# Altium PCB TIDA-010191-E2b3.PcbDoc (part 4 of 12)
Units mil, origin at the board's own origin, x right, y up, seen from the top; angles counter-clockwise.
Board outline 9842.52 x 9842.4 mil, 6 copper layers (Layer 1 - Top Layer, Layer 2 - GND Layer, Layer 3 - Signal, Layer 4 - Signal, Layer 5 - GND, Bottom Layer), stack 59.9 mil thick; 1178 components, 642 nets, 3329 pads, 2967 vias.
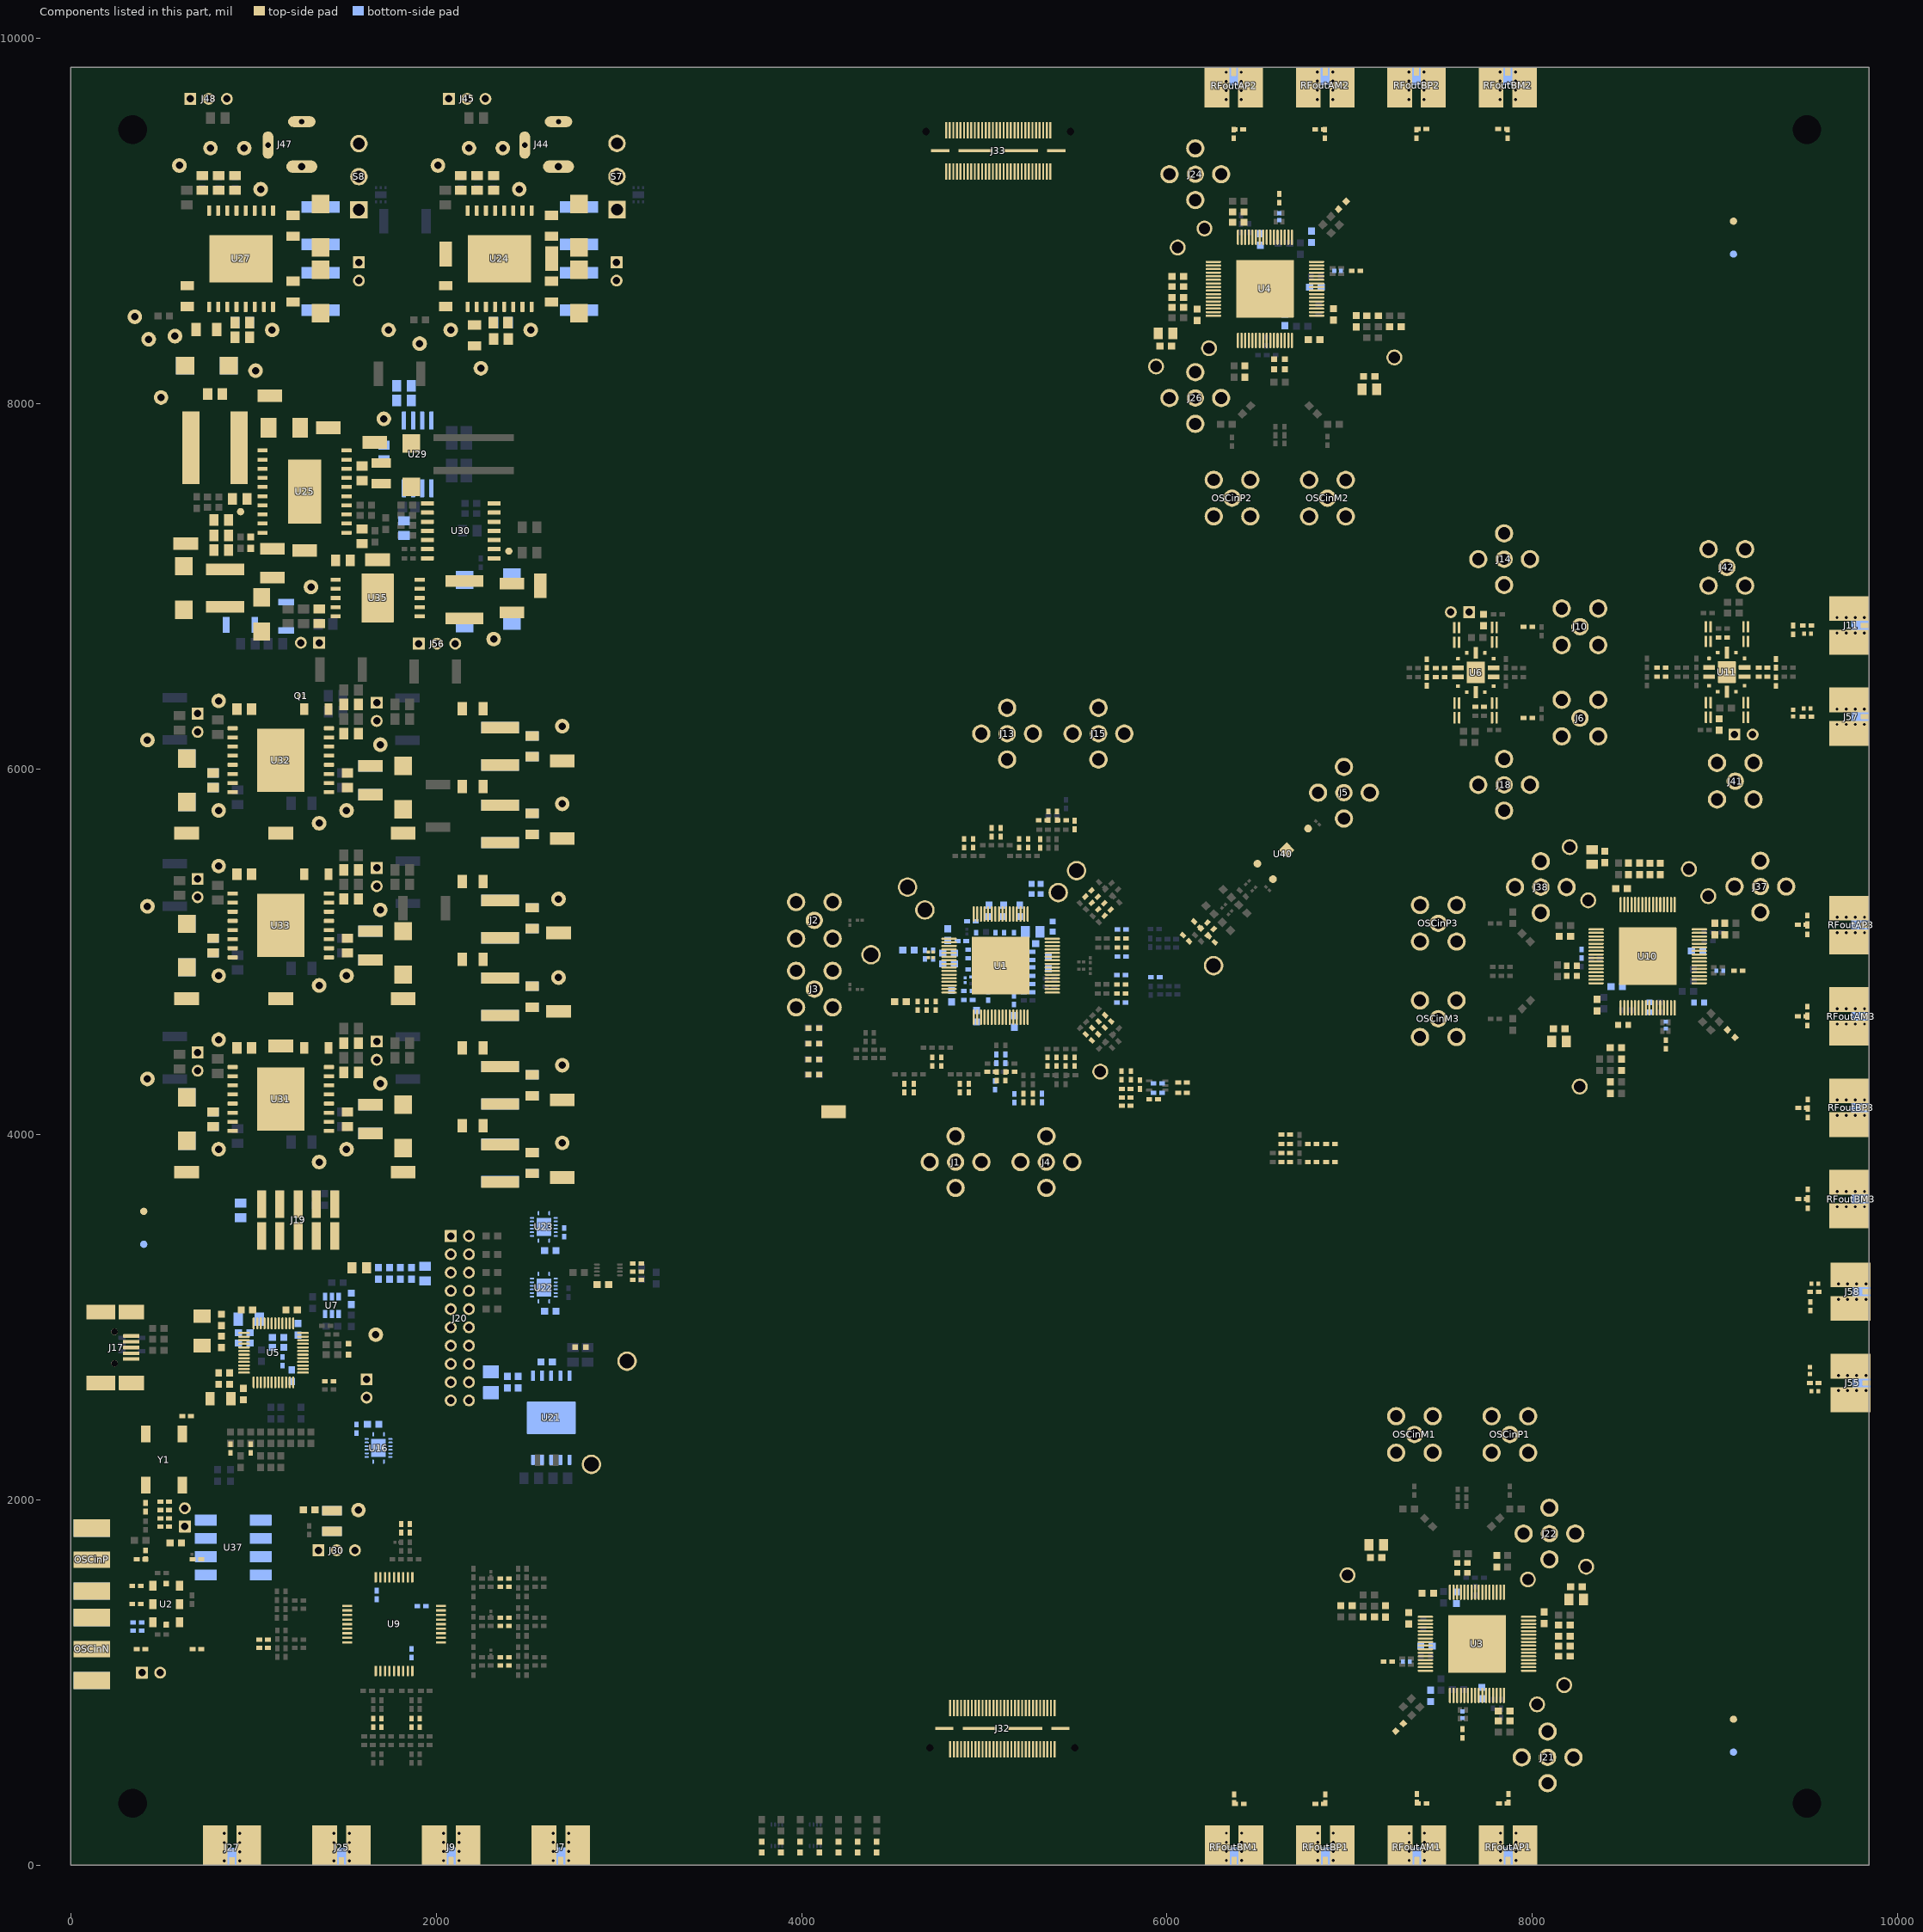
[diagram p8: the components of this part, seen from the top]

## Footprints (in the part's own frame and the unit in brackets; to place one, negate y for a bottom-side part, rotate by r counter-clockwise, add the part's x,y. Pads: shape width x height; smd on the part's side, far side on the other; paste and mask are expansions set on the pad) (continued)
FCI_52601-S10-8LF [mil] "FCI Electronics"
  rect 150x50 smd: 1(-87.5,200) 2(86.5,200) 3(-87.5,100) 4(87.5,100) 5(-87.5,0) 6(87.5,0) 7(-87.5,-100) 8(87.5,-100) 9(-87.5,-200) 10(87.5,-200)
  silkscreen extent -175,-396 176,397, body extent -172,-395 173,395, height 496
FFK0014A [mm] "LCCC-14"
  rrect20% 0.5x0.5 smd: 1(-2.725,1.27) 3(-2.725,-1.27) 4(-1.905,-2.475) 7(1.905,-2.475) 8(2.725,-1.27) 10(2.725,1.27) 11(1.905,2.475) 14(-1.905,2.475)
  rrect16% 1.65x0.64 smd: 2(-2.725,0) 9(2.725,0)
  rrect16% 0.64x1.65 smd: 5(-0.635,-2.475) 6(0.635,-2.475) 12(0.635,2.475) 13(-0.635,2.475)
  rrect4% 3x2.5 smd paste-4: 15(0,0)
  Layer 1 - Top Layer region: -2.225,2.05 -2.225,3.25 -2.221,3.269 -2.21,3.285 -2.194,3.296 -2.175,3.3 -2.175,3.3 -1.635,3.3 -1.616,3.296 -1.6,3.285 -1.589,3.269 -1.585,3.25 -1.585,3.25 -1.585,1.7 -1.589,1.681 -1.6,1.665 -1.616,1.654 -1.635,1.65 -1.635,1.65 -1.825,1.65
  Layer 1 - Top Layer region: 1.635,1.65 1.616,1.654 1.6,1.665 1.589,1.681 1.585,1.7 1.585,1.7 1.585,3.25 1.589,3.269 1.6,3.285 1.616,3.296 1.635,3.3 1.635,3.3 2.175,3.3 2.194,3.296 2.21,3.285 2.221,3.269 2.225,3.25 2.225,3.25 2.225,2.05 1.825,1.65
  Layer 1 - Top Layer region: 1.9,-1.19 1.9,-1 1.904,-0.981 1.915,-0.965 1.931,-0.954 1.95,-0.95 1.95,-0.95 3.5,-0.95 3.519,-0.954 3.535,-0.965 3.546,-0.981 3.55,-1 3.55,-1 3.55,-1.54 3.546,-1.559 3.535,-1.575 3.519,-1.586 3.5,-1.59 3.5,-1.59 2.3,-1.59
  Layer 1 - Top Layer region: 1.9,1 1.904,0.981 1.915,0.965 1.931,0.954 1.95,0.95 1.95,0.95 3.5,0.95 3.519,0.954 3.535,0.965 3.546,0.981 3.55,1 3.55,1 3.55,1.54 3.546,1.559 3.535,1.575 3.519,1.586 3.5,1.59 3.5,1.59 2.3,1.59 1.9,1.19
  Layer 1 - Top Layer region: 1.585,-3.25 1.585,-1.7 1.589,-1.681 1.6,-1.665 1.616,-1.654 1.635,-1.65 1.635,-1.65 1.825,-1.65 2.225,-2.05 2.225,-3.25 2.221,-3.269 2.21,-3.285 2.194,-3.296 2.175,-3.3 2.175,-3.3 1.635,-3.3 1.616,-3.296 1.6,-3.285 1.589,-3.269 1.585,-3.25
  Layer 1 - Top Layer region: -2.225,-3.25 -2.221,-3.269 -2.21,-3.285 -2.194,-3.296 -2.175,-3.3 -2.175,-3.3 -1.635,-3.3 -1.616,-3.296 -1.6,-3.285 -1.589,-3.269 -1.585,-3.25 -1.585,-3.25 -1.585,-1.7 -1.589,-1.681 -1.6,-1.665 -1.616,-1.654 -1.635,-1.65 -1.635,-1.65 -1.825,-1.65 -2.225,-2.05
  Layer 1 - Top Layer region: -3.55,-1.54 -3.55,-1 -3.546,-0.981 -3.535,-0.965 -3.519,-0.954 -3.5,-0.95 -3.5,-0.95 -1.95,-0.95 -1.931,-0.954 -1.915,-0.965 -1.904,-0.981 -1.9,-1 -1.9,-1 -1.9,-1.19 -2.3,-1.59 -3.5,-1.59 -3.519,-1.586 -3.535,-1.575 -3.546,-1.559 -3.55,-1.54
  Layer 1 - Top Layer region: -3.5,0.95 -3.519,0.954 -3.535,0.965 -3.546,0.981 -3.55,1 -3.55,1 -3.55,1.54 -3.546,1.559 -3.535,1.575 -3.519,1.586 -3.5,1.59 -3.5,1.59 -2.3,1.59 -1.9,1.19 -1.9,1 -1.904,0.981 -1.915,0.965 -1.931,0.954 -1.95,0.95 -1.95,0.95
  body extent -3,-2.75 3,2.75, height 1.63
Fiducial10-20 [mm]
  round 1 smd mask+0.5: 1(0,0)
  Layer 1 - Top Layer keep-out circle w1.178: c0,0 r0.5
FP-678038020_CONN_USB-MFG [mm]
  rrect20% 2.25x0.5 smd paste+0 mask+0: 1(3.725,1.6) 2(3.725,0.8) 3(3.725,0) 4(3.725,-0.8) 5(3.725,-1.6)
  rrect5% 4x2.05 smd paste+0 mask+0: 6(-0.5,4.925) 8(-0.5,-4.925)
  rrect5% 3.5x2.05 smd paste+0 mask+0: 7(3.75,4.925) 9(3.75,-4.925)
  round 0.9 hole 0.9 unplated paste-1000 mask+0: ""(1.4,-2.2) ""(1.4,2.2)
  Keep-Out Layer region: -2.5,-3.1 -1.3,-3.1 -1.3,3.1 -2.5,3.1
  silkscreen extent 4.62,-3.52 5.77,3.52, body extent -4.72,-6.05 5.6,6.05, height 0.25
FP-AD4PS-1+_SMT8-MFG [mm]
  rrect7% 3.05x1.52 smd paste+0 mask+0: 1(-3.81,3.81) 2(-3.81,1.27) 3(-3.81,-1.27) 4(-3.81,-3.81) 5(3.81,-3.81) 6(3.81,-1.27) 7(3.81,1.27) 8(3.81,3.81)
  silkscreen extent -6.06,-4.89 3.94,4.89, body extent -5.04,-4.89 5.04,4.89, height 5.46
HBD0064A_Custom_A [mm] "CFP, 64-Leads, Body 10.9x10.9mm, Pitch 0.5 mm"
  rrect100% 2.15x0.3 smd: 1(-7.175,3.75) 2(-7.175,3.25) 3(-7.175,2.75) 4(-7.175,2.25) 5(-7.175,1.75) 6(-7.175,1.25) 7(-7.175,0.75) 8(-7.175,0.25) 9(-7.175,-0.25) 10(-7.175,-0.75) 11(-7.175,-1.25) 12(-7.175,-1.75) 13(-7.175,-2.25) 14(-7.175,-2.75) 15(-7.175,-3.25) 16(-7.175,-3.75) 33(7.175,-3.75) 34(7.175,-3.25) 35(7.175,-2.75) 36(7.175,-2.25) 37(7.175,-1.75) 38(7.175,-1.25) 39(7.175,-0.75) 40(7.175,-0.25) 41(7.175,0.25) 42(7.175,0.75) 43(7.175,1.25) 44(7.175,1.75) 45(7.175,2.25) 46(7.175,2.75) 47(7.175,3.25) 48(7.175,3.75)
  rrect100% 0.3x2.15 smd: 17(-3.75,-7.175) 18(-3.25,-7.175) 19(-2.75,-7.175) 20(-2.25,-7.175) 21(-1.75,-7.175) 22(-1.25,-7.175) 23(-0.75,-7.175) 24(-0.25,-7.175) 25(0.25,-7.175) 26(0.75,-7.175) 27(1.25,-7.175) 28(1.75,-7.175) 29(2.25,-7.175) 30(2.75,-7.175) 31(3.25,-7.175) 32(3.75,-7.175) 49(3.75,7.175) 50(3.25,7.175) 51(2.75,7.175) 52(2.25,7.175) 53(1.75,7.175) 54(1.25,7.175) 55(0.75,7.175) 56(0.25,7.175) 57(-0.25,7.175) 58(-0.75,7.175) 59(-1.25,7.175) 60(-1.75,7.175) 61(-2.25,7.175) 62(-2.75,7.175) 63(-3.25,7.175) 64(-3.75,7.175)
  rrect1% 8x8 smd: 65(0,0)
  silkscreen extent -7.3,-5.7 5.7,5.7, body extent -7.86,-7.86 7.87,7.87, height 2.31
HBE0064A-MFG [mm]
  rrect100% 2.15x0.3 smd paste+0 mask+0: 1(-7.175,3.75) 2(-7.175,3.25) 3(-7.175,2.75) 4(-7.175,2.25) 5(-7.175,1.75) 6(-7.175,1.25) 7(-7.175,0.75) 8(-7.175,0.25) 9(-7.175,-0.25) 10(-7.175,-0.75) 11(-7.175,-1.25) 12(-7.175,-1.75) 13(-7.175,-2.25) 14(-7.175,-2.75) 15(-7.175,-3.25) 16(-7.175,-3.75) 33(7.175,-3.75) 34(7.175,-3.25) 35(7.175,-2.75) 36(7.175,-2.25) 37(7.175,-1.75) 38(7.175,-1.25) 39(7.175,-0.75) 40(7.175,-0.25) 41(7.175,0.25) 42(7.175,0.75) 43(7.175,1.25) 44(7.175,1.75) 45(7.175,2.25) 46(7.175,2.75) 47(7.175,3.25) 48(7.175,3.75)
  rrect100% 0.3x2.15 smd paste+0 mask+0: 17(-3.75,-7.175) 18(-3.25,-7.175) 19(-2.75,-7.175) 20(-2.25,-7.175) 21(-1.75,-7.175) 22(-1.25,-7.175) 23(-0.75,-7.175) 24(-0.25,-7.175) 25(0.25,-7.175) 26(0.75,-7.175) 27(1.25,-7.175) 28(1.75,-7.175) 29(2.25,-7.175) 30(2.75,-7.175) 31(3.25,-7.175) 32(3.75,-7.175) 49(3.75,7.175) 50(3.25,7.175) 51(2.75,7.175) 52(2.25,7.175) 53(1.75,7.175) 54(1.25,7.175) 55(0.75,7.175) 56(0.25,7.175) 57(-0.25,7.175) 58(-0.75,7.175) 59(-1.25,7.175) 60(-1.75,7.175) 61(-2.25,7.175) 62(-2.75,7.175) 63(-3.25,7.175) 64(-3.75,7.175)
  rrect1% 8x8 smd paste+0 mask+0: 65(0,0)
  silkscreen extent -7.3,-5.52 5.52,5.52, body extent -8.35,-8.35 8.35,8.35, height 0.25
HFG0036A_Custom_A [mil] "QFP, 36-Leads, Body 9.078x9.078mm, Pitch 0.635mm"
  rrect31% 56x12.5 smd: 1(-256.5,100) 2(-256.5,75) 3(-256.5,50) 4(-256.5,25) 5(-256.5,0) 6(-256.5,-25) 7(-256.5,-50) 8(-256.5,-75) 9(-256.5,-100) 19(256.5,-100) 20(256.5,-75) 21(256.5,-50) 22(256.5,-25) 23(256.5,0) 24(256.5,25) 25(256.5,50) 26(256.5,75) 27(256.5,100)
  rrect31% 12.5x56 smd: 10(-100,-256.5) 11(-75,-256.5) 12(-50,-256.5) 13(-25,-256.5) 14(0,-256.5) 15(25,-256.5) 16(50,-256.5) 17(75,-256.5) 18(100,-256.5) 28(100,256.5) 29(75,256.5) 30(50,256.5) 31(25,256.5) 32(0,256.5) 33(-25,256.5) 34(-50,256.5) 35(-75,256.5) 36(-100,256.5)
  silkscreen extent -189,-189 189,189, body extent -179,-179 179,179, height 79
HKH0020A_CUSTOM_A [mm] "SMD, 20-Leads, Body 12.7x7.38mm, Pitch 1.27mm"
  rrect18% 1.42x0.55 smd: 1(-5.84,5.715) 2(-5.84,4.445) 3(-5.84,3.175) 4(-5.84,1.905) 5(-5.84,0.635) 6(-5.84,-0.635) 7(-5.84,-1.905) 8(-5.84,-3.175) 9(-5.84,-4.445) 10(-5.84,-5.715) 11(5.84,-5.715) 12(5.84,-4.445) 13(5.84,-3.175) 14(5.84,-1.905) 15(5.84,-0.635) 16(5.84,0.635) 17(5.84,1.905) 18(5.84,3.175) 19(5.84,4.445) 20(5.84,5.715)
  rrect2% 4.62x8.89 smd paste-8: 21(0,0)
  silkscreen extent -3.8,-6.48 3.8,6.8, body extent -6.48,-6.48 6.48,6.48, height 2.23
HKR0016A_Custom_A [mil] "16-Leads, Body 11.3x9.9mm, Pitch 1.27mm, Thermal Pad 9x6.78mm"
  rrect25% 56x22 smd: 1(-263.5,175) 2(-263.5,125) 3(-263.5,75) 4(-263.5,25) 5(-263.5,-25) 6(-263.5,-75) 7(-263.5,-125) 8(-263.5,-175) 9(263.5,-175) 10(263.5,-125) 11(263.5,-75) 12(263.5,-25) 13(263.5,25) 14(263.5,75) 15(263.5,125) 16(263.5,175)
  rect 259.45x346.46 smd: 17(0,0)
  silkscreen extent -273,-222 194,221, body extent -290,-222 290,222, height 92
HKU0010_CUSTOM_A#1 [mm] "HKU custom footprint"
  rrect18% 1.42x0.55 smd: 1(-5.84,2.54) 2(-5.84,1.27) 3(-5.84,0) 4(-5.84,-1.27) 5(-5.84,-2.54) 6(5.84,-2.54) 7(5.84,-1.27) 8(5.84,0) 9(5.84,1.27) 10(5.84,2.54)
  rrect11% 0.95x0.95 on Bottom Paste: 11(-1.725,-2.875) 11(-1.725,-1.725) 11(-1.725,-0.575) 11(-1.725,0.575) 11(-1.725,1.725) 11(-1.725,2.875) 11(-0.575,-2.875) 11(-0.575,-1.725) 11(-0.575,-0.575) 11(-0.575,0.575) 11(-0.575,1.725) 11(-0.575,2.875) 11(0.575,-2.875) 11(0.575,-1.725) 11(0.575,-0.575) 11(0.575,0.575) 11(0.575,1.725) 11(0.575,2.875) 11(1.725,-2.875) 11(1.725,-1.725) 11(1.725,-0.575) 11(1.725,0.575) 11(1.725,1.725) 11(1.725,2.875)
  rrect4% 4.5x6.82 smd paste-3 mask-0.05: 11(0,0)
  silkscreen extent -3.56,-3.68 3.56,3.68, body extent -5.84,-3.6 5.84,3.6, height 2.59
HKU0010_CUSTOM_A#2 [mm] "HKU custom footprint"
  rrect18% 1.42x0.55 smd: 1(-5.84,2.54) 2(-5.84,1.27) 3(-5.84,0) 4(-5.84,-1.27) 5(-5.84,-2.54) 6(5.84,-2.54) 7(5.84,-1.27) 8(5.84,0) 9(5.84,1.27) 10(5.84,2.54)
  rrect11% 0.95x0.95 on Top Paste: 11(-1.725,1.725) 11(-1.725,2.875) 11(-1.725,-0.575) 11(-1.725,0.575) 11(-1.725,-2.875) 11(-1.725,-1.725) 11(-0.575,2.875) 11(-0.575,1.725) 11(-0.575,0.575) 11(-0.575,-0.575) 11(-0.575,-1.725) 11(-0.575,-2.875) 11(0.575,2.875) 11(0.575,1.725) 11(0.575,0.575) 11(0.575,-0.575) 11(0.575,-1.725) 11(0.575,-2.875) 11(1.725,1.725) 11(1.725,2.875) 11(1.725,-0.575) 11(1.725,0.575) 11(1.725,-2.875) 11(1.725,-1.725)
  rrect4% 4.5x6.82 smd paste-3 mask-0.05: 11(0,0)
  silkscreen extent -3.56,-3.68 3.56,3.68, body extent -5.84,-3.6 5.84,3.6, height 2.59
HKX0008A_Custom_A [mm] "CFP, 8-Leads, Body 6.475x6.485mm, Pitch 1.27mm"
  rrect17% 2.5x0.6 smd: 1(-4.7,1.905) 2(-4.7,0.635) 3(-4.7,-0.635) 4(-4.7,-1.905) 5(4.7,-1.905) 6(4.7,-0.635) 7(4.7,0.635) 8(4.7,1.905)
  silkscreen extent -5.5,-3.36 3.37,3.36, body extent -3.25,-3.24 3.25,3.24, height 2.51
IND_LQG15H [mm] "MuRata"
  rect 0.55x0.6 smd: 1(-0.475,0) 2(0.475,0)
  silkscreen extent -1.3,-0.3 -0.95,0.3, body extent -0.52,-0.27 0.52,0.27, height 0.55
Johnson_142-0701-20x [mil] "Johnson Components recommended land pattern"
  round 95 hole 62: 1(0,0)
  round 100 hole 67: 2(100,100) 3(100,-100) 4(-100,-100) 5(-100,100)
  body extent -156,-156 156,156, height 375
Johnson_142-0771-831 [mil] "JACK, SMA, 50 Ohm, Gold, Edge Mount"
  rect 28.5x45 smd: 1(0,-22.5)
  rect 135.75x218 smd: 2(-92.12,-109) 3(92.13,-109)
  round 16 hole 16: 2(-42,-25) 2(-42,-75) 2(-42,-125) 2(-42,-175) 3(42,-25) 3(42,-75) 3(42,-125) 3(42,-175)
  rect 270x97.5 smd far side: 4(0,-48.75)
  body extent -124,-179 123,375, height 131
Keystone1573-2 [mm] "Double Turret"
  round 2.7 hole 2.05: 1(0,0)
  silkscreen extent -1.73,-1.73 1.73,1.73, body extent -1.18,-1.18 1.17,1.18, height 4.72
Keystone5000 [mil] "For Keystone 500x miniature loop terminals"
  round 80 hole 40: 1(0,0)
  silkscreen extent -52,-52 52,52, body extent -49,-49 49,49, height 182
Keystone5002 [mil] "For Keystone 500x miniature loop terminals"
  round 80 hole 40: 1(0,0)
  silkscreen extent -52,-52 52,52, body extent -49,-49 49,49, height 182
Keystone5007 [mil] "Keystone Compact loops"
  round 87 hole 63: 1(0,0)
  silkscreen extent -70,-70 70,70, body extent -63,-63 62,63, height 225
Label_650x200 [mil] "Thermal Transfer Label"
  round 1 on Mech13: 0(0,0)
  silkscreen extent -325,-100 325,100, body extent -325,-100 325,100, height 1
LQFP-48_N [mm] "QFP, 48-Leads, Body 7x7mm, Pitch 0.5mm, IPC Medium Density"
  oval 1.65x0.3 smd: 1(-4.1,2.75) 2(-4.1,2.25) 3(-4.1,1.75) 4(-4.1,1.25) 5(-4.1,0.75) 6(-4.1,0.25) 7(-4.1,-0.25) 8(-4.1,-0.75) 9(-4.1,-1.25) 10(-4.1,-1.75) 11(-4.1,-2.25) 12(-4.1,-2.75) 25(4.1,-2.75) 26(4.1,-2.25) 27(4.1,-1.75) 28(4.1,-1.25) 29(4.1,-0.75) 30(4.1,-0.25) 31(4.1,0.25) 32(4.1,0.75) 33(4.1,1.25) 34(4.1,1.75) 35(4.1,2.25) 36(4.1,2.75)
  oval 0.3x1.65 smd: 13(-2.75,-4.1) 14(-2.25,-4.1) 15(-1.75,-4.1) 16(-1.25,-4.1) 17(-0.75,-4.1) 18(-0.25,-4.1) 19(0.25,-4.1) 20(0.75,-4.1) 21(1.25,-4.1) 22(1.75,-4.1) 23(2.25,-4.1) 24(2.75,-4.1) 37(2.75,4.1) 38(2.25,4.1) 39(1.75,4.1) 40(1.25,4.1) 41(0.75,4.1) 42(0.25,4.1) 43(-0.25,4.1) 44(-0.75,4.1) 45(-1.25,4.1) 46(-1.75,4.1) 47(-2.25,4.1) 48(-2.75,4.1)
  silkscreen extent -4.22,-2.88 2.88,3.57, body extent -3.5,-3.5 3.5,3.5, height 1.61
LTST-C191_Green [mm] "Lite-On"
  rect 0.8x0.8 smd: 1(-0.75,0) 2(0.75,0)
  silkscreen extent -1.1,-0.8 1.8,0.8, body extent -0.85,-0.45 0.85,0.45, height 0.65
Marki_BAL-0006SMG [mil] "SMD, 3-Leads, Body 320x320mil"
  round 42 smd: 1(0,166) 2(60,-166) 3(-60,-166)
  rect 60x60 smd: 4(0,0)
  Layer 1 - Top Layer region: -100.42,-180 -100.42,-160 -93.24,-142.03 -78.63,-129.36 -59.83,-124.79 -41.03,-129.36 -26.42,-142.03 -19.24,-160 -19.24,-160 -19.24,-160 -19.24,-180 19.24,-180 19.24,-160 19.24,-160 26.42,-142.03 41.03,-129.36 59.83,-124.79 78.63,-129.36 93.24,-142.03 100.42,-160 100.42,-160 100.42,-180 180,-180 180,180 40.46,180 40.46,160 40.46,160 33.29,142.03 18.68,129.36 -0.12,124.79 -18.92,129.36 -33.54,142.03 -40.71,160 -40.71,160 -40.71,180 -180,180 -180,-180
  Multi-Layer region: 84.36,84 53.36,99 44.64,81 75.64,66
  Multi-Layer region: -75.64,66 -44.64,81 -53.36,99 -84.36,84
  Multi-Layer region: 129.98,-126.34 104,-141.34 114,-158.66 139.98,-143.66
  Multi-Layer region: -139.98,-143.66 -114,-158.66 -104,-141.34 -129.98,-126.34
  Multi-Layer region: -49,80 -31,80 -31,100 -49,100
  Multi-Layer region: 49,100 31,100 31,80 49,80
  Multi-Layer region: -11,-160 11,-160 11,-140 -11,-140
  body extent -160,-160 160,160, height 155
NAC0014A_L [mm] "CFP-14"
  rrect17% 1.8x0.6 smd: 1(-4.65,3.81) 2(-4.65,2.54) 3(-4.65,1.27) 4(-4.65,0) 5(-4.65,-1.27) 6(-4.65,-2.54) 7(-4.65,-3.81) 8(4.65,-3.81) 9(4.65,-2.54) 10(4.65,-1.27) 11(4.65,0) 12(4.65,1.27) 13(4.65,2.54) 14(4.65,3.81)
  silkscreen extent -4.78,-4.97 3.35,4.97, body extent -5.21,-4.95 5.21,4.95, height 1.99
Net-Tie_0805_HV_NoOverlay [mil] "0805_HV pads tied by 10mil copper trace which can be cut.  An 0805 part can be placed on pads."
  rect 50x63 smd paste-25: 1(-40,0) 2(40,0)
  Layer 1 - Top Layer lines w10: 16,0 -16,0
  Layer 1 - Top Layer keep-out lines w1: 22,30.91 22,-30.91 ; 14.96,30.91 -14.96,30.91 ; 14.96,-30.91 -14.96,-30.91 ; -22,30.91 -22,-30.91
OSC_CVHD-950-4 [mil] "Crystek recommended land pattern 2011-02-22 Rev H"
  rect 90x50 smd: 1(-140,100) 2(-140,-100) 3(140,-100) 4(140,100)
  silkscreen extent -200,-300 200,300, body extent -180,-280 180,280, height 209
Pb-Free_Overlay_Small [mil]
  silkscreen extent -46,-46 46,46
RGY0016A [mm] "QFN, 16-Leads, Body 4x3.5mm, Pitch 0.5mm, Thermal Pad 2.55x2.05mm, TI Recommended"
  oval 0.24x0.6 smd: 1(-0.75,1.9) 8(-0.75,-1.9) 9(0.75,-1.9) 16(0.75,1.9)
  oval 0.6x0.24 smd: 2(-1.65,1.25) 3(-1.65,0.75) 4(-1.65,0.25) 5(-1.65,-0.25) 6(-1.65,-0.75) 7(-1.65,-1.25) 10(1.65,-1.25) 11(1.65,-0.75) 12(1.65,-0.25) 13(1.65,0.25) 14(1.65,0.75) 15(1.65,1.25)
  rect 2.05x2.55 smd paste-1.025: 17(0,0)
  silkscreen extent -1.97,-2.22 1.97,2.23, body extent -1.75,-2 1.75,2, height 1
Samtec_HTSW-102-07-G-S [mm] "Samtec 100mil, 1x2, 230 mil above insulator"
  rrect6% 1.65x1.65 hole 1.016: 1(-1.27,0)
  round 1.65 hole 1.016: 2(1.27,0)
  silkscreen extent -3.3,-1.27 2.54,1.27, body extent -2.54,-1.27 2.54,1.27, height 8.38
Samtec_HTSW-103-07-G-S [mm] "Samtec 100mil, 1x3, 230 mil above insulator"
  rrect6% 1.65x1.65 hole 1.016: 1(-2.54,0)
  round 1.65 hole 1.016: 2(0,0) 3(2.54,0)
  silkscreen extent -4.57,-1.27 3.81,1.27, body extent -3.81,-1.27 3.81,1.27, height 8.38
Samtec_QSH-030-01-X-D-A [mm] "Receptacle, 0.5 mm, 30x2, TH"
  rect 2.27x0.279 smd: 1(-2.865,7.25) 2(2.865,7.25) 3(-2.865,6.75) 4(2.865,6.75) 5(-2.865,6.25) 6(2.865,6.25) 7(-2.865,5.75) 8(2.865,5.75) 9(-2.865,5.25) 10(2.865,5.25) 11(-2.865,4.75) 12(2.865,4.75) 13(-2.865,4.25) 14(2.865,4.25) 15(-2.865,3.75) 16(2.865,3.75) 17(-2.865,3.25) 18(2.865,3.25) 19(-2.865,2.75) 20(2.865,2.75) 21(-2.865,2.25) 22(2.865,2.25) 23(-2.865,1.75) 24(2.865,1.75) 25(-2.865,1.25) 26(2.865,1.25) 27(-2.865,0.75) 28(2.865,0.75) 29(-2.865,0.25) 30(2.865,0.25) 31(-2.865,-0.25) 32(2.865,-0.25) 33(-2.865,-0.75) 34(2.865,-0.75) 35(-2.865,-1.25) 36(2.865,-1.25) 37(-2.865,-1.75) 38(2.865,-1.75) 39(-2.865,-2.25) 40(2.865,-2.25) 41(-2.865,-2.75) 42(2.865,-2.75) 43(-2.865,-3.25) 44(2.865,-3.25) 45(-2.865,-3.75) 46(2.865,-3.75) 47(-2.865,-4.25) 48(2.865,-4.25) 49(-2.865,-4.75) 50(2.865,-4.75) 51(-2.865,-5.25) 52(2.865,-5.25) 53(-2.865,-5.75) 54(2.865,-5.75) 55(-2.865,-6.25) 56(2.865,-6.25) 57(-2.865,-6.75) 58(2.865,-6.75) 59(-2.865,-7.25) 60(2.865,-7.25)
  round 0 hole 1.02 unplated: MH1(2.67,10.065) MH2(2.67,-10.065)
  rect 0.43x2.54 smd: MP1(0,8.065) MP4(0,-8.065)
  rect 0.43x4.7 smd: MP2(0,3.175) MP3(0,-3.175)
  silkscreen extent -3.9,-10.66 3.62,10.66, body extent -3.75,-10.64 3.75,10.67, height 3.25
SIA0008B [mm] "SIP 8-Leads, Body 5x7mm"
  rrect17% 1x0.6 on Top Paste: 1(-1.85,2.14) 1(-1.85,2.94) 2(-1.85,-0.4) 2(-1.85,0.4) 3(-1.85,-2.94) 3(-1.85,-2.14) 4(1.85,-2.94) 4(1.85,-2.14) 5(1.85,-0.4) 5(1.85,0.4) 6(1.85,2.14) 6(1.85,2.94)
  rrect10% 1x1.4 smd paste-0.5: 1(-1.85,2.54) 2(-1.85,0) 3(-1.85,-2.54) 4(1.85,-2.54) 5(1.85,0) 6(1.85,2.54)
  rrect12% 0.8x0.8 smd: 7(0,2.865) 8(0,-2.865)
  silkscreen extent -2.64,-3.63 2.64,3.63, body extent -2.56,-3.56 2.56,3.56, height 1.13
SMB [mil] "Molded Diode, 2-Leads, Body 5.4x3.6mm, IPC Medium Density, based on OnSemi component dimensions"
  rect 85x107.99 smd: 1(-87.01,0) 2(87.01,0)
  silkscreen extent -155,-82 125,82, body extent -106,-71 106,71, height 91
SOT-23-6 [mm] "SOT23, 6-Leads, Body 3.0x1.7mm, Pitch 0.95mm, Lead Span 2.9mm, IPC Medium Density"
  rect 1.1x0.65 smd: 1(-1.2,0.95) 2(-1.2,0) 3(-1.2,-0.95) 4(1.2,-0.95) 5(1.2,0) 6(1.2,0.95)
  silkscreen extent -0.25,-1.55 0.25,1.55, body extent -1.5,-1.5 1.5,1.5, height 1.3
SPC02SYAN [mil] "SULLINS"
  round 1 on Mech3: 0(0,0)
  body extent -98,-47 99,47, height 366
ST_LCC-2D [mm] "ST Microelectronics"
  rect 0.9x2.2 smd: 1(-2,0) 2(2,0)
  silkscreen extent -1.25,-1.25 2.95,1.25, body extent -2.4,-1.07 2.4,1.05, height 2.2
"SW_ L101011MS02Q" [mm] "SWITCH SLIDE sPST 4A PCB"
  rect 2.416x2.416 hole 1.65: 1(2.857,4.6)
  round 2.416 hole 1.65: 2(2.857,0) 3(2.858,-4.6)
  silkscreen extent -5.4,-9.55 5.4,9.55, body extent -5.39,-9.55 5.39,9.55, height 14.18
TCBS-6-01 [mil] "Richco Plastics"
  round 60 hole 157 unplated: 1(0,0)
  body extent -180,-156 180,156, height 375
Testpoint_Keystone_Miniature [mil] "Miniature SMT test point"
  rect 135x70 smd: 1(0,0)
  silkscreen extent -78,-46 78,45, body extent -52,-20 52,20, height 61
TP_SM_1MM [mm] "1mm Test Point, SMT"
  round 1 smd paste-0.5: 1(0,0)
TSW-110-07-G-D [mm] "Samtec 100mil, 2x10, 230 mil above insulator"
  rrect6% 1.65x1.65 hole 1.016: 1(-11.43,-1.27)
  round 1.65 hole 1.016: 2(-11.43,1.27) 3(-8.89,-1.27) 4(-8.89,1.27) 5(-6.35,-1.27) 6(-6.35,1.27) 7(-3.81,-1.27) 8(-3.81,1.27) 9(-1.27,-1.27) 10(-1.27,1.27) 11(1.27,-1.27) 12(1.27,1.27) 13(3.81,-1.27) 14(3.81,1.27) 15(6.35,-1.27) 16(6.35,1.27) 17(8.89,-1.27) 18(8.89,1.27) 19(11.43,-1.27) 20(11.43,1.27)
  silkscreen extent -13.72,-2.54 12.7,2.54, body extent -12.7,-2.54 12.7,2.54, height 8.38
WEEE_Minimum [mil] "WEEElie bin"
  silkscreen extent -95,-172 99,104
XTAL_ABM3 [mm] "Abracon recommended land pattern 12.28.10"
  rect 1.9x2.4 smd: 1(-2.05,0) 2(2.05,0)
  silkscreen extent -2.67,-1.78 2.67,1.78, body extent -2.6,-1.7 2.6,1.7, height 1.3

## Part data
C1 C3 C4 C5 C6 C9 C12 C15 C16 C19 C26 C31 C38 C39 C79 C80 C85 C86 C87 C88 C89 C184 C185 C186: library part CMP-0006295-2, "CAP, CERM, 0.1 uF, 25 V, +/- 20%, X7R, 0402", Cap_Case=0402, Manufacturer=TDK, PartNumber=C1005X7R1E104M050BB, Supplier Part Number 1=445-7349-1-ND, TempCo=X7R, Tolerance_%=20%, Value1=Unknown, Value2=25V, ValueDisplayed=0.1uF
C2 C24 C29: library part CMP-0006641-2, "CAP, CERM, 0.1 uF, 16 V, +/- 10%, X7R, 0402", Cap_Case=0402, Manufacturer=MuRata, PartNumber=GRM155R71C104KA88D, Supplier Part Number 1=490-3261-1-ND, TempCo=X7R, Tolerance_%=10%, Value1=Unknown, Value2=16V, ValueDisplayed=0.1uF
C7: library part CMP-0009662-3, "CAP, CERM, 47 pF, 25 V, +/- 5%, C0G/NP0, 0201", Cap_Case=0201, Manufacturer=MuRata, PartNumber=GRM0335C1E470JA01D, Supplier Part Number 1=490-1256-1-ND, TempCo=C0G/NP0, Tolerance_%=5%, Value1=Unknown, Value2=25V, ValueDisplayed=47pF
C8: library part CMP-0064907-1, "CAP, CERM, 3900 pF, 10 V,+/- 10%, X5R, 0201", Cap_Case=0201, Manufacturer=AVX, PartNumber=0201ZD392KAT2A, Supplier Part Number 1=478-1046-1-ND, TempCo=X5R, Tolerance_%=10%, Value1=Unknown, Value2=10V, ValueDisplayed=3900pF
C10 C11 C23 C27 C28 C32 C33 C34 C35: library part CMP-0006300-2, "CAP, CERM, 1 uF, 10 V, +/- 10%, X7S, 0402", Cap_Case=0402, Manufacturer=TDK, PartNumber=C1005X7S1A105K050BC, Supplier Part Number 1=445-9116-1-ND, TempCo=X7S, Tolerance_%=10%, Value1="0.011416 ohm", Value2=10V, ValueDisplayed=1uF
C13 C52 C53 C122 C123 C161 C162: "CAP, CERM, 10 uF, 10 V, +/- 10%, X5R, 0805", Cap_Case=0805, Manufacturer=Kemet, PartNumber=C0805C106K8PACTU, Supplier Part Number 1=399-4925-1-ND, TempCo=X5R, Tolerance_%=10%, Value1="0.003 ohm", Value2=10V, ValueDisplayed=10uF
C14 C108 C109 C110 C111 C113 C114 C115 C117 C124 C199: library part CMP-0006856-6, "CAP, CERM, 0.1 uF, 25 V, +/- 5%, X7R, 0603", Cap_Case=0603, Manufacturer=Kemet, PartNumber=C0603C104J3RACTU, Supplier Part Number 1=399-1282-1-ND, TempCo=X7R, Tolerance_%=5%, Value1=Unknown, Value2=25V, ValueDisplayed=0.1uF
C17: library part CMP-0006271-2, "CAP, CERM, 0.68 uF, 10 V, +/- 10%, X5R, 0402", Cap_Case=0402, Manufacturer=TDK, PartNumber=C1005X5R1A684K050BB, Supplier Part Number 1=445-172461-1-ND, TempCo=X5R, Tolerance_%=10%, Value1=Unknown, Value2=10V, ValueDisplayed=0.68uF
C18 C20 C21: library part CMP-0006919-4, "CAP, CERM, 33 pF, 50 V, +/- 5%, C0G/NP0, 0603", Cap_Case=0603, Manufacturer=Kemet, PartNumber=C0603C330J5GACTU, Supplier Part Number 1=399-1055-1-ND, TempCo=C0G/NP0, Tolerance_%=5%, Value1=Unknown, Value2=50V, ValueDisplayed=33pF
C22: "CAP, CERM, 100 pF, 50 V, +/- 1%, C0G/NP0, 0402", Cap_Case=0402, Manufacturer=AVX, PartNumber=04025A101FAT2A, Supplier Part Number 1=478-3658-1-ND, TempCo=C0G/NP0, Tolerance_%=1%, Value1=Unknown, Value2=50V, ValueDisplayed=100pF
C25 C30 C188: library part CMP-0006658-2, "CAP, CERM, 0.01 uF, 25 V, +/- 10%, X7R, 0402", Cap_Case=0402, Manufacturer=MuRata, PartNumber=GRM155R71E103KA01D, Supplier Part Number 1=490-1312-1-ND, TempCo=X7R, Tolerance_%=10%, Value1=Unknown, Value2=25V, ValueDisplayed=0.01uF
C36 C37: library part CMP-0009690-3, "CAP, CERM, 0.1 uF, 6.3 V, +/- 10%, X5R, 0201", Cap_Case=0201, Manufacturer=MuRata, PartNumber=GRM033R60J104KE19D, Supplier Part Number 1=490-3167-1-ND, TempCo=X5R, Tolerance_%=10%, Value1=Unknown, Value2=6.3V, ValueDisplayed=0.1uF
C40: "CAP, CERM, 0.1 uF, 25 V, +/- 20%, X7R, 0402", Cap_Case=0402, Manufacturer=TDK, PartNumber=C1005X7R1E104M050BB, Supplier Part Number 1=445-7349-1-ND, TempCo=X7R, Tolerance_%=20%, Value1=Unknown, Value2=25V, ValueDisplayed=0.1uF
C41 C43 C74 C75 C209 C210: "CAP, CERM, 2200 pF, 50 V, +/- 20%, X7R, 0306", Cap_Case=0306, Manufacturer=MuRata, PartNumber=LLL185R71H222MA01L, Supplier Part Number 1=490-4311-1-ND, TempCo=X7R, Tolerance_%=20%, Value1=Unknown, Value2=50V, ValueDisplayed=2200pF
C42 C63 C197 C200: library part CMP-0009490-2, "CAP, CERM, 0.01 uF, 25 V, +/- 20%, X7R, 0306", Cap_Case=0306, Manufacturer=MuRata, PartNumber=LLL185R71E103MA01L, Supplier Part Number 1=490-4315-1-ND, TempCo=X7R, Tolerance_%=20%, Value1=Unknown, Value2=25V, ValueDisplayed=0.01uF
C44 C45 C48 C57 C61 C64 C118 C131 C141 C142 C153 C156 C158 C166 C173 C181 C189 C192: library part CMP-0006210-2, "CAP, CERM, 0.01 uF, 16 V, +/- 10%, X7R, 0402", Cap_Case=0402, Manufacturer="AT Ceramics", PartNumber=520L103KT16T, Supplier Part Number 1=1284-1540-1-ND, TempCo=X7R, Tolerance_%=10%, Value1=Unknown, Value2=16V, ValueDisplayed=0.01uF
C46 C47 C49 C55 C56 C98 C100 C128 C129 C130 C138 C139 C143 C145 C167 C169: "CAP, CERM, 1 uF, 16 V, +/- 10%, X7R, 0603", Cap_Case=0603, Manufacturer=TDK, PartNumber=C1608X7R1C105K080AC, Supplier Part Number 1=445-1604-1-ND, TempCo=X7R, Tolerance_%=10%, Value1="0.0057 ohm", Value2=16V, ValueDisplayed=1uF
C50 C140: "CAP, CERM, 0.1 uF, 16 V, +/- 5%, X7R, 0603", Cap_Case=0603, Manufacturer=AVX, PartNumber=0603YC104JAT2A, Supplier Part Number 1=478-3726-1-ND, TempCo=X7R, Tolerance_%=5%, Value1="0.039 ohm", Value2=16V, ValueDisplayed=0.1uF
C51 C54 C71 C72 C121 C127 C154 C160 C163 C191 C193 C194 C195: library part CMP-0006808-4, "CAP, CERM, 0.1 uF, 16 V, +/- 5%, X7R, 0603", Cap_Case=0603, Manufacturer=AVX, PartNumber=0603YC104JAT2A, Supplier Part Number 1=478-3726-1-ND, TempCo=X7R, Tolerance_%=5%, Value1="0.039 ohm", Value2=16V, ValueDisplayed=0.1uF
C58 C150 C170: library part CMP-0007192-4, "CAP, CERM, 1800 pF, 50 V, +/- 5%, C0G/NP0, 0603", Cap_Case=0603, Manufacturer=MuRata, PartNumber=GRM1885C1H182JA01D, Supplier Part Number 1=490-1457-1-ND, TempCo=C0G/NP0, Tolerance_%=5%, Value1=Unknown, Value2=50V, ValueDisplayed=1800pF
C59 C149 C171: "CAP, CERM, 300 pF, 100 V, +/- 5%, C0G/NP0, 0603", Cap_Case=0603, Manufacturer=MuRata, PartNumber=GRM1885C2A301JA01D, Supplier Part Number 1=490-1362-1-ND, TempCo=C0G/NP0, Tolerance_%=5%, Value1=Unknown, Value2=100V, ValueDisplayed=300pF
C60 C146 C172: library part CMP-0007460-5, "CAP, CERM, 0.056 uF, 50 V, +/- 10%, X7R, 0603", Cap_Case=0603, Manufacturer=MuRata, PartNumber=GRM188R71H563KA93D, Supplier Part Number 1=81-GRM188R71H563KA93, TempCo=X7R, Tolerance_%=10%, Value1=Unknown, Value2=50V, ValueDisplayed=0.056uF
C62 C148 C175: library part CMP-0064973-4, "CAP, CERM, 1500 pF, 50 V,+/- 5%, C0G/NP0, 0603", Cap_Case=0603, Manufacturer=MuRata, PartNumber=GRM1885C1H152JA01J, Supplier Part Number 1=490-11448-1-ND, TempCo=C0G/NP0, Tolerance_%=5%, Value1=Unknown, Value2=50V, ValueDisplayed=1500pF
C65 C66 C69 C70 C77 C105 C133 C134 C202 C203 C204 C207 C212 C331 C332 C333: library part CMP-0006619-2, "CAP, CERM, 1 uF, 35 V, +/- 10%, X5R, 0402", Cap_Case=0402, Manufacturer=MuRata, Supplier Part Number 1=490-10019-1-ND, TempCo=X5R, Tolerance_%=10%, Value1=Unknown, Value2=35V, ValueDisplayed=1uF
C67 C68 C205 C206: library part CMP-0006206-2, "CAP, CERM, 0.3 pF, 50 V, +/- 30%, C0G/NP0, 0402", Cap_Case=0402, Manufacturer="Johanson Technology", TempCo=C0G/NP0, Tolerance_%=30%, Value1=Unknown, Value2=50V, ValueDisplayed=0.3pF
C73 C76 C208 C211: "CAP, CERM, 0.01 uF, 25 V, +/- 20%, X7R, 0306", Cap_Case=0306, Manufacturer=MuRata, PartNumber=LLL185R71E103MA01L, Supplier Part Number 1=490-4315-1-ND, TempCo=X7R, Tolerance_%=20%, Value1=Unknown, Value2=25V, ValueDisplayed=0.01uF
C78 C213: library part CMP-0007377-4, "CAP, CERM, 0.01 uF, 16 V, +/- 10%, X7R, 0603", Cap_Case=0603, Manufacturer=MuRata, Supplier Part Number 1=490-1525-1-ND, TempCo=X7R, Tolerance_%=10%, Value1=Unknown, Value2=16V, ValueDisplayed=0.01uF
C83: library part CMP-0006663-2, "CAP, CERM, 2200 pF, 25 V, +/- 10%, X7R, 0402", Cap_Case=0402, Manufacturer=MuRata, PartNumber=GRM155R71E222KA01D, Supplier Part Number 1=490-5419-1-ND, TempCo=X7R, Tolerance_%=10%, Value1=Unknown, Value2=25V, ValueDisplayed=2200pF
C84: library part CMP-0006408-2, "CAP, CERM, 10 pF, 50 V, +/- 5%, C0G/NP0, 0402", Cap_Case=0402, Manufacturer=MuRata, PartNumber=GRM1555C1H100JA01D, Supplier Part Number 1=81-GRM1555C1H100JA1D, TempCo=C0G/NP0, Tolerance_%=5%, Value1=Unknown, Value2=50V, ValueDisplayed=10pF
C92 C132 C316 C317 C318 C319 C320 C321 C322 C323 C324 C325: "CAP, CERM, 0.01 uF, 16 V, +/- 10%, X7R, 0402", Cap_Case=0402, Manufacturer="AT Ceramics", PartNumber=520L103KT16T, Supplier Part Number 1=1284-1540-1-ND, TempCo=X7R, Tolerance_%=10%, Value1=Unknown, Value2=16V, ValueDisplayed=0.01uF
C93: library part CMP-0009207-2, "CAP, CERM, 22 uF, 10 V, +/- 10%, X5R, 1210", Cap_Case=1210, Manufacturer=MuRata, Supplier Part Number 1=81-GRM32ER61A226KE20, TempCo=X5R, Tolerance_%=10%, Value1="0.002 ohm", Value2=10V, ValueDisplayed=22uF
C94: library part CMP-0009080-2, "CAP, CERM, 10 uF, 10 V, +/- 10%, X5R, 1210", Cap_Case=1210, Manufacturer=Kemet, Supplier Part Number 1=80-C1210C106K8P, TempCo=X5R, Tolerance_%=10%, Value1="0.008 ohm", Value2=10V, ValueDisplayed=10uF
C95: library part CMP-0006223-2, "CAP, CERM, 0.1 uF, 16 V, +/- 20%, X5R, 0402", Cap_Case=0402, Manufacturer="Wurth Elektronik", Supplier Part Number 1=40Y4445, TempCo=X5R, Tolerance_%=20%, Value1=Unknown, Value2=16V, ValueDisplayed=0.1uF
C96: library part CMP-0006596-2, "CAP, CERM, 0.033 uF, 16 V, +/- 10%, X5R, 0402", Cap_Case=0402, Manufacturer=MuRata, Supplier Part Number 1=490-5416-1-ND, TempCo=X5R, Tolerance_%=10%, Value1=Unknown, Value2=16V, ValueDisplayed=0.033uF
C97: library part CMP-0006352-2, "CAP, CERM, 0.01 uF, 25 V, +/- 10%, X7R, 0402", Cap_Case=0402, Manufacturer=MuRata, Supplier Part Number 1=490-6043-2-ND, TempCo=X7R, Tolerance_%=10%, Value1=Unknown, Value2=25V, ValueDisplayed=0.01uF
C99 C101 C102 C103 C104 C106 C107 C112 C144 C147 C151 C152 C168 C174 C180 C182 C183 C190: "CAP, CERM, 10 uF, 10 V, +/- 20%, X5R, 0603", Cap_Case=0603, Manufacturer=TDK, PartNumber=C1608X5R1A106M080AC, Supplier Part Number 1=445-6853-1-ND, TempCo=X5R, Tolerance_%=20%, Value1="0.0078 ohm", Value2=10V, ValueDisplayed=10uF
C125 C126: library part CMP-0007259-4, "CAP, CERM, 27 pF, 100 V, +/- 5%, C0G/NP0, 0603", Cap_Case=0603, Manufacturer=MuRata, PartNumber=GRM1885C2A270JA01D, Supplier Part Number 1=490-1337-1-ND, TempCo=C0G/NP0, Tolerance_%=5%, Value1=Unknown, Value2=100V, ValueDisplayed=27pF
C135 C136 C137 C347: library part CMP-0007985-2, "CAP, CERM, 470 pF, 50 V, +/- 5%, C0G/NP0, 0805", Cap_Case=0805, Manufacturer=TDK, Supplier Part Number 1=445-13359-1-ND, TempCo=C0G/NP0, Tolerance_%=5%, Value1=Unknown, Value2=50V, ValueDisplayed=470pF
C155 C157 C159 C164 C165: library part CMP-0007037-4, "CAP, CERM, 1 uF, 16 V, +/- 10%, X7R, 0603", Cap_Case=0603, Manufacturer=TDK, PartNumber=C1608X7R1C105K080AC, Supplier Part Number 1=445-1604-1-ND, TempCo=X7R, Tolerance_%=10%, Value1="0.0057 ohm", Value2=16V, ValueDisplayed=1uF
C187: library part CMP-0006258-2, "CAP, CERM, 4.7 uF, 6.3 V, +/- 20%, X5R, 0402", Cap_Case=0402, Manufacturer=TDK, PartNumber=C1005X5R0J475M050BC, Supplier Part Number 1=445-7395-1-ND, TempCo=X5R, Tolerance_%=20%, Value1=Unknown, Value2=6.3V, ValueDisplayed=4.7uF
C196 C221 C222: library part CMP-0006856-6, "CAP, CERM, 0.1 uF, 25 V, +/- 5%, X7R, 0603", Cap_Case=0603, Manufacturer=Kemet, Supplier Part Number 1=399-1282-1-ND, TempCo=X7R, Tolerance_%=5%, Value1=Unknown, Value2=25V, ValueDisplayed=0.1uF
C198 C201: library part CMP-0009493-2, "CAP, CERM, 2200 pF, 50 V, +/- 20%, X7R, 0306", Cap_Case=0306, Manufacturer=MuRata, PartNumber=LLL185R71H222MA01L, Supplier Part Number 1=490-4311-1-ND, TempCo=X7R, Tolerance_%=20%, Value1=Unknown, Value2=50V, ValueDisplayed=2200pF
C217 C218: library part CMP-0007130-4, "CAP, CERM, 100 pF, 100 V, +/- 5%, C0G/NP0, AEC-Q200 Grade 1, 0603", Cap_Case=0603, Manufacturer=MuRata, Supplier Part Number 1=490-4771-1-ND, TempCo=C0G/NP0, Tolerance_%=5%, Value1=Unknown, Value2=100V, ValueDisplayed=100pF
C219: library part CMP-0860183-1, "CAP, CERM, 1 µF, 16 V,+/- 10%, X5R, 0603", Cap_Case=0603, Manufacturer=AVX, TempCo=X5R, Tolerance_%=10%, Value2=16V, ValueDisplayed=1µF
C220: library part CMP-0011510-2, "CAP, TA, 10 uF, 10 V, +/- 20%, 2.5 ohm, SMD", Cap_Case=B, Manufacturer=Vishay-Sprague, Supplier Part Number 1=718-1119-1-ND, Tolerance_%=20%, Value1="2.5 ohm", Value2=10V, ValueDisplayed=10uF
C223 C249: library part CMP-0007711-2, "CAP, CERM, 1000 pF, 50 V, +/- 5%, X7R, 0805", Cap_Case=0805, Manufacturer=Kemet, Supplier Part Number 1=399-1149-1-ND, TempCo=X7R, Tolerance_%=5%, Value1="0.384 ohm", Value2=50V, ValueDisplayed=1000pF
C224 C241 C242 C243 C250 C258 C259 C260: library part CMP-0007566-2, "CAP, CERM, 0.1 uF, 25 V, +/- 5%, X7R, 0805", Cap_Case=0805, Manufacturer=AVX, Supplier Part Number 1=08053C104JAZ2A-ND, TempCo=X7R, Tolerance_%=5%, Value1=Unknown, Value2=25V, ValueDisplayed=0.1uF
C225 C248 C251: library part CMP-0079724-1, "CAP, CERM, 0.033 µF, 25 V,+/- 10%, X7R, 0805", Cap_Case=0805, Manufacturer="Presidio Components", TempCo=X7R, Tolerance_%=10%, Value2=25V, ValueDisplayed=0.033µF
C226: library part CMP-0079721-1, "CAP, CERM, 0.01 µF, 25 V,+/- 10%, X7R, 0603", Cap_Case=0603, Manufacturer="Presidio Components", TempCo=X7R, Tolerance_%=10%, Value2=25V, ValueDisplayed=0.01µF
C227 C237 C252 C255: library part CMP-0012657-3, "CAP, Tantalum Polymer, 330 uF, 10 V, +/- 20%, 0.006 ohm, 7343-43 SMD", Cap_Case=7343-43, Manufacturer=Kemet, Supplier Part Number 1=399-4134-1-ND, Tolerance_%=20%, Value1="0.006 ohm", Value2=10V, ValueDisplayed=330uF
C228 C238 C254 C256 C267 C268 C280 C281 C286 C287 C299 C300 C305 C306 C339 C340: library part CMP-0008532-2, "CAP, CERM, 0.1 uF, 50 V, +/- 5%, X7R, 1206", Cap_Case=1206, Manufacturer=AVX, Supplier Part Number 1=478-3797-1-ND, TempCo=X7R, Tolerance_%=5%, Value1="0.037 ohm", Value2=50V, ValueDisplayed=0.1uF
C229 C245: library part CMP-0079725-1, "CAP, CERM, 680 pF, 10 V,+/- 10%, X7R, 0805", Cap_Case=0805, Manufacturer="Presidio Components", TempCo=X7R, Tolerance_%=10%, Value2=10V, ValueDisplayed=680pF
C230 C231 C233: library part CMP-0079639-1, "CAP, Tantalum Polymer, 330 µF, 10 V,+/- 20%, 7343-43 SMD", Cap_Case=7343-43, Manufacturer=Kemet, Tolerance_%=20%, Value2=10V, ValueDisplayed=330µF
C232: library part CMP-0079722-1, "CAP, CERM, 0.1 µF, 25 V,+/- 10%, X7R, 0805", Cap_Case=0805, Manufacturer="Presidio Components", TempCo=X7R, Tolerance_%=10%, Value2=25V, ValueDisplayed=0.1µF
C234 C240 C253 C257 C270 C283 C289 C302 C308 C342 C349 C354: library part CMP-0009304-2, "CAP, CERM, 10 uF, 100 V, +/- 20%, X7R, 2220", Cap_Case=2220, Manufacturer=AVX, Supplier Part Number 1=478-9622-1-ND, TempCo=X7R, Tolerance_%=20%, Value1=Unknown, Value2=100V, ValueDisplayed=10uF
C235: library part CMP-0009088-1, "CAP, CERM, 4.7 uF, 10 V, +/- 10%, X7R, 1210", Cap_Case=1210, Manufacturer=Kemet, Supplier Part Number 1=399-8239-1-ND, TempCo=X7R, Tolerance_%=10%, Value1=Unknown, Value2=10V, ValueDisplayed=4.7uF
C236 C244: library part CMP-0007631-2, "CAP, CERM, 0.1 uF, 50 V, +/- 5%, X7R, 0805", Cap_Case=0805, Manufacturer=AVX, Supplier Part Number 1=478-3352-1-ND, TempCo=X7R, Tolerance_%=5%, Value1="0.024 ohm", Value2=50V, ValueDisplayed=0.1uF
C239: library part CMP-0007880-2, "CAP, CERM, 0.47 uF, 50 V, +/- 10%, X7R, 0805", Cap_Case=0805, Manufacturer=TDK, Supplier Part Number 1=445-7543-1-ND, TempCo=X7R, Tolerance_%=10%, Value1="0.022012 ohm", Value2=50V, ValueDisplayed=0.47uF
C246 C247 C262 C263: library part CMP-0082630-1, "CAP, CERM, 2000 pF, 50 V,+/- 5%, C0G/NP0, 1206", Cap_Case=1206, Manufacturer=AVX, Supplier Part Number 1=478-6053-1-ND, TempCo=C0G/NP0, Tolerance_%=5%, Value2=50V, ValueDisplayed=2000pF
C261 C264 C266: library part CMP-0007716-2, "CAP, CERM, 0.01 uF, 100 V, +/- 1%, C0G/NP0, 0805", Cap_Case=0805, Manufacturer=Kemet, Supplier Part Number 1=399-11160-1-ND, TempCo=C0G/NP0, Tolerance_%=1%, Value1=Unknown, Value2=100V, ValueDisplayed=0.01uF
C265: library part CMP-0007722-2, "CAP, CERM, 0.1 uF, 100 V, +/- 10%, X7R, 0805", Cap_Case=0805, Manufacturer=Kemet, Supplier Part Number 1=399-3486-1-ND, TempCo=X7R, Tolerance_%=10%, Value1="0.064 ohm", Value2=100V, ValueDisplayed=0.1uF
C269 C282 C288 C301 C307 C341: library part CMP-0080078-1, "CAP, CERM, 33 µF, 25 V,+/- 20%, X7R, 2220", Cap_Case=2220, Manufacturer=Chemi-Con, Supplier Part Number 1=565-4694-1-ND, TempCo=X7R, Tolerance_%=20%, Value2=25V, ValueDisplayed=33µF
C271 C290 C295 C309 C314: library part CMP-0008376-2, "CAP, CERM, 0.01 uF, 250 V, +/- 10%, X7R, 0805", Cap_Case=0805, Manufacturer=MuRata, PartNumber=GRM21BR72E103KW03L, Supplier Part Number 1=490-3534-1-ND, TempCo=X7R, Tolerance_%=10%, Value1=Unknown, Value2=250V, ValueDisplayed=0.01uF
C272 C291 C310: library part CMP-0011937-2, "CAP, TA, 10 uF, 50 V, +/- 10%, 0.5 ohm, SMD", Cap_Case=E, Manufacturer=AVX, PartNumber=TPSE106K050R0500, Supplier Part Number 1=478-2424-1-ND, Tolerance_%=10%, Value1="0.5 ohm", Value2=50V, ValueDisplayed=10uF
C273 C274 C292 C293 C311 C312 C352: "CAP, TA, 220 uF, 16 V, +/- 20%, 0.1 ohm, SMD", Cap_Case=E, Manufacturer=AVX, PartNumber=TPSE227M016R0100, Supplier Part Number 1=478-4131-1-ND, Tolerance_%=20%, Value1="0.1 ohm", Value2=16V, ValueDisplayed=220uF
C275 C277 C294 C296 C313 C315 C348: library part CMP-0007723-2, "CAP, CERM, 0.1 uF, 25 V, +/- 10%, X7R, 0805", Cap_Case=0805, Manufacturer=Kemet, Supplier Part Number 1=399-1168-1-ND, TempCo=X7R, Tolerance_%=10%, Value1="0.064 ohm", Value2=25V, ValueDisplayed=0.1uF
C276: "CAP, CERM, 0.01 uF, 250 V, +/- 10%, X7R, 0805", Cap_Case=0805, Manufacturer=MuRata, PartNumber=GRM21BR72E103KW03L, Supplier Part Number 1=490-3534-1-ND, TempCo=X7R, Tolerance_%=10%, Value1=Unknown, Value2=250V, ValueDisplayed=0.01uF
C278 C279 C297 C298 C326 C334 C350: library part CMP-0009392-2, "CAP, CERM, 3.3 uF, 50 V, +/- 10%, X7R, AEC-Q200 Grade 1,", Cap_Case=1812_220, Manufacturer=TDK, Supplier Part Number 1=445-7905-1-ND, TempCo=X7R, Tolerance_%=10%, Value1="0.004024 ohm", Value2=50V, ValueDisplayed=3.3uF
C284 C343: library part CMP-0008070-2, "CAP, CERM, 2000 pF, 50 V, +/- 5%, C0G/NP0, 0805", Cap_Case=0805, Manufacturer=MuRata, PartNumber=GRM2165C1H202JA01D, Supplier Part Number 1=490-1627-1-ND, TempCo=C0G/NP0, Tolerance_%=5%, Value1=Unknown, Value2=50V, ValueDisplayed=2000pF
C285 C344: library part CMP-0064950-2, "CAP, CERM, 0.1 uF, 25 V,+/- 5%, C0G/NP0, 1206", Cap_Case=1206, Manufacturer=MuRata, PartNumber=GRM31C5C1E104JA01L, Supplier Part Number 1=490-1767-1-ND, TempCo=C0G/NP0, Tolerance_%=5%, Value1=Unknown, Value2=25V, ValueDisplayed=0.1uF
C303: "CAP, CERM, 2000 pF, 50 V, +/- 5%, C0G/NP0, 0805", Cap_Case=0805, Manufacturer=MuRata, PartNumber=GRM2165C1H202JA01D, Supplier Part Number 1=490-1627-1-ND, TempCo=C0G/NP0, Tolerance_%=5%, Value1=Unknown, Value2=50V, ValueDisplayed=2000pF
C304: "CAP, CERM, 0.1 uF, 25 V,+/- 5%, C0G/NP0, 1206", Cap_Case=1206, Manufacturer=MuRata, PartNumber=GRM31C5C1E104JA01L, Supplier Part Number 1=490-1767-1-ND, TempCo=C0G/NP0, Tolerance_%=5%, Value1=Unknown, Value2=25V, ValueDisplayed=0.1uF
C327 C328 C329: library part CMP-0007044-5, "CAP, CERM, 0.1 uF, 50 V, +/- 10%, X7R, 0603", Cap_Case=0603, Manufacturer=TDK, PartNumber=C1608X7R1H104K080AA, Supplier Part Number 1=445-1314-1-ND, TempCo=X7R, Tolerance_%=10%, Value1="0.0296 ohm", Value2=50V, ValueDisplayed=0.1uF
C335: library part CMP-0007043-4, "CAP, CERM, 0.01 uF, 50 V, +/- 10%, X7R, 0603", Cap_Case=0603, Manufacturer=TDK, PartNumber=C1608X7R1H103K080AA, Supplier Part Number 1=445-1311-1-ND, TempCo=X7R, Tolerance_%=10%, Value1="0.0539 ohm", Value2=50V, ValueDisplayed=0.01uF
C337: library part CMP-0008141-3, "CAP, CERM, 1000 pF, 25 V, +/- 10%, X7R, 0805", Cap_Case=0805, Manufacturer=MuRata, PartNumber=GRM216R71E102KA01D, Supplier Part Number 1=GRM216R71E102KA01D-ND, TempCo=X7R, Tolerance_%=10%, Value1=Unknown, Value2=25V, ValueDisplayed=1000pF
C345: library part CMP-0011664-2, "CAP, TA, 33 uF, 10 V, +/- 10%, 0.375 ohm, SMD", Cap_Case=C, Manufacturer=AVX, Supplier Part Number 1=478-1770-1-ND, Tolerance_%=10%, Value1="0.375 ohm", Value2=10V, ValueDisplayed=33uF
C346: library part CMP-0011882-2, "CAP, TA, 22 uF, 25 V, +/- 10%, 0.1 ohm, SMD", Cap_Case=D, Manufacturer=AVX, Supplier Part Number 1=478-3331-1-ND, Tolerance_%=10%, Value1="0.1 ohm", Value2=25V, ValueDisplayed=22uF
C351: library part CMP-0011872-2, "CAP, TA, 15 uF, 35 V, +/- 10%, 0.3 ohm, SMD", Cap_Case=D, Manufacturer=AVX, Supplier Part Number 1=478-1780-1-ND, Tolerance_%=10%, Value1="0.3 ohm", Value2=35V, ValueDisplayed=15uF
C353: library part CMP-0009354-2, "CAP, CERM, 1 uF, 100 V, +/- 10%, X7R, 1812", Cap_Case=1812_254, Manufacturer=TDK, Supplier Part Number 1=445-1438-1-ND, TempCo=X7R, Tolerance_%=10%, Value1="0.005865 ohm", Value2=100V, ValueDisplayed=1uF
C355 C356: library part CMP-0006658-2, "CAP, CERM, 0.01 uF, 25 V, +/- 10%, X7R, 0402", Cap_Case=0402, Manufacturer=MuRata, Supplier Part Number 1=490-1312-1-ND, TempCo=X7R, Tolerance_%=10%, Value1=Unknown, Value2=25V, ValueDisplayed=0.01uF
CE_TP1 CE_TP2 CE_TP3 RMPCLK1 RMPCLK2 RMPCLK3 RMPDIR1 RMPDIR2 RMPDIR3 SYNC Vcc_TP1 Vcc_TP2 Vcc_TP3 Vtune_TP1 Vtune_TP2 Vtune_TP3: library part CMP-0055144-2, "Test Point, Compact, White, TH", Color=White, Manufacturer="Keystone Electronics", Supplier Part Number 1=36-5007-ND
D1 D2 D3 D4 D10: library part CMP-0002891-3, "LED, Green, SMD", Color=green, Manufacturer=Lite-On, PartNumber=LTST-C191TGKT, Value1=W, Value2=3.2V
D5 D6 D13: "LED, Green, SMD", Color=green, Manufacturer=Lite-On, PartNumber=LTST-C191TGKT, Value1=W, Value2=3.2V
D7 D14 D15 D16 D17 D18 D19 D20: library part CMP-0078478-2, "LED, Green, SMD", Color=Green, Manufacturer=Lite-On, Power_TotalModule=75mW, Value1=0.075W, Value2=2V
D12: library part CMP-0028348-2, "Diode, Schottky, 20 V, 3 A, SMB", Manufacturer="Diodes Inc.", Value1=3A, Value2=0.5V
D21 D22: library part CMP-0076902-2, "Diode, Switching, 100 V, 0.3 A, LCC-2D", Manufacturer=STMicroelectronics, Value1=0.3A, Value2=1.2V
FID1 FID2 FID3 FID4 FID5 FID6: library part CMP-0077181-1, "Fiducial mark.  There is nothing to buy or mount.", Manufacturer=N/A
J1 J2 J3 J4 J5 J6 J10 J13 J14 J15 J18 J41 J42: library part CMP-0055819-1, "Connector, SMA, TH", Manufacturer="Cinch Connectivity", PartNumber=142-0701-201, Supplier Part Number 1=J500-ND
J7 J9 J11 J25 J27 J55 J57 J58 RFoutAM1 RFoutAM2 RFoutAM3 RFoutAP1 RFoutAP2 RFoutAP3 RFoutBM1 RFoutBM2 RFoutBM3 RFoutBP1 RFoutBP2 RFoutBP3: library part CMP-0055844-3, "JACK, SMA, 50 Ohm, Gold, Edge Mount", Color=Gold, Manufacturer="Cinch Connectivity", Supplier Part Number 1=J808-ND, Voltage_V=170V
J8 J12 J16 J39 J40 J43 J46 J49 J50 J51 J52 J53 J54 J59: library part CMP-0075483-1, "Header, 100mil, 2x1, Gold, TH", Manufacturer=Samtec, Supplier Part Number 1=SAM8736-ND
J17: library part CMP-0088148-1, "MOLEX 67803-8020 MINI USB, 2.0 OTG TYPE AB, RCPT, TH", Current_A=1A, Manufacturer=Molex, Voltage_V=30V
J19: "Header (shrouded), 100mil, 5x2, Gold, SMT", Manufacturer=FCI, PartNumber=52601-S10-8LF, Supplier Part Number 1=609-3593-ND
J20: library part CMP-0075421-2, "Header, 100mil, 10x2, Gold, TH", Color=Black, Current_A=6.3A, Manufacturer=Samtec, Supplier Part Number 1=SAM1028-10-ND, Voltage_V=550V
J21 J22 J24 J26 J37 J38 OSCinM1 OSCinM2 OSCinP1 OSCinP2: library part CMP-0055819-1, "Connector, SMA, TH", Manufacturer="Cinch Connectivity", Supplier Part Number 1=J500-ND
J30 J45 J48 J56: library part CMP-0075484-1, "Header, 100mil, 3x1, Gold, TH", Manufacturer=Samtec, Supplier Part Number 1=HTSW-103-07-G-S-ND
J32 J33: "Receptacle, 0.5 mm, 30x2, Gold, TH", Color=Black, Manufacturer=Samtec, PartNumber=QSH-030-01-L-D-A, Supplier Part Number 1=SAM8180-ND
J44 J47: library part CMP-0074940-1, "Power Jack, mini, 2.1mm OD, R/A, TH", Manufacturer=Switchcraft, Supplier Part Number 1=SC1313-ND
L1 L2 L3 L4 L5 L6 L7 L8 L9 L10 L13 L30 L31: library part CMP-0003352-2, "Ferrite Bead, 120 ohm @ 100 MHz, 3 A, 0603", Manufacturer=MuRata, PartNumber=BLM18SG121TN1D, Supplier Part Number 1=490-3996-1-ND, Value1="0.025 ohm", Value2=3A, ValueDisplayed="120 ohm"
L11 L12 L18 L19 L21 L22: "Inductor, Multilayer, Air Core, 18 nH, 0.3 A, 0.36 ohm, SMD", Manufacturer=MuRata, PartNumber=LQG15HS18NJ02D, Supplier Part Number 1=490-2626-1-ND, Value1="0.36 ohm", Value2=0.3A, ValueDisplayed=18nH
L14 L32 L37 L38 L39 L40: library part CMP-0058615-1, "Inductor, Multilayer, Air Core, 1 nH, 0.3 A, 0.07 ohm, SMD", Manufacturer=MuRata, PartNumber=LQG15HS1N0S02D, Supplier Part Number 1=490-2610-1-ND, Value1="0.07 ohm", Value2=0.3A, ValueDisplayed=1nH
L15 L16 L24 L25 L26 L27 L28 L29: library part CMP-0003365-1, "Ferrite Bead, 120 ohm @ 100 MHz, 3.5 A, 1206", Manufacturer=MuRata, PartNumber=BLM31PG121SN1L, Supplier Part Number 1=490-1056-1-ND, Value1="0.02 ohm", Value2=3.5A, ValueDisplayed="120 ohm"
L17: library part CMP-0003370-2, "Ferrite Bead, 80 ohm @ 100 MHz, 0.6 A, 0603", Manufacturer="Samsung Electro-Mechanics", Supplier Part Number 1=1276-6386-1-ND, Value1="0.1 ohm", Value2=0.6A, ValueDisplayed="80 ohm"
L23: library part CMP-0061180-1, "Inductor, Composite, 2.2 uH, 18.4 A, 0.0028 ohm, SMD", Manufacturer="Coilcraft CPS", Value1="0.0028 ohm", Value2=18.4A, ValueDisplayed=2.2uH
LBL1: library part CMP-0003625-1, "Thermal Transfer Printable Labels, 0.650\" W x 0.200\" H - 10,000 per roll", Manufacturer=Brady, PartNumber=THT-14-423-10, Supplier Part Number 1=97C5133
Logo1: library part CMP-0074839-1
Logo2: library part CMP-0074847-1, "FCC_disclaimer"
Logo3: library part CMP-0074769-1
Logo4: library part CMP-0074840-1, "ESD Susceptible Symbol"
NT1 NT2: library part CMP-0078142-5, "Single point connection between nets.", Manufacturer=N/A
OSCinM3 OSCinP3: "Connector, SMA, TH", Manufacturer="Cinch Connectivity", PartNumber=142-0701-201, Supplier Part Number 1=J500-ND
OSCinN OSCinP: library part CMP-0055822-3, "Connector, End launch SMA, 50 ohm, SMT", Manufacturer="Cinch Connectivity", PartNumber=142-0701-851, Supplier Part Number 1=J658-ND
Q1: library part CMP-0000409-2, "Transistor, NPN, 40 V, 0.2 A, 3-UFDFN", Manufacturer="Diodes Inc.", Supplier Part Number 1=MMBT3904LP-7BDICT-ND, Value1="0.2 A", Value2=400
R1 R2 R3 R4 R6 R7 R8 R9 R10 R19 R20 R25 R27 R33 R37 R39 R41 R42 R45 R46 R54 R55 R56 R57 R62 R63 R70 R114 R115 R141 R142 R144 R146 R148 R165 R167 R172 R173 R182 R183 R184 R191 R192 R193 R194 R195 R196 R197 R200 R201 R202 R218 R219 R223 R229 R234 R236 R237 R241 R248 R266 R275 R276 R278 R284 R285 R290 R291 R297 R298 R335 R336 R337 R338 R339 R340 R341 R344 R345 R346 R347 R357 R366 R371 R381 R390 R391 R393 R394 R478 R481 R482 R483 R484: library part CMP-0026822-3, "RES, 0, 5%, 0.063 W, AEC-Q200 Grade 0, 0402", Manufacturer=Vishay-Dale, PartNumber=CRCW04020000Z0ED, Power_W=63mW, Supplier Part Number 1=541-0.0JCT-ND, TempCo="200 ppm/C", Tolerance_%=5%, Value2=0.063W, Value_Code=0000, ValueDisplayed=0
